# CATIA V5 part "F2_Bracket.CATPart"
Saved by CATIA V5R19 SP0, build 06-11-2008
Part number: F2
Revision: ANY
Definition: UNKNOWN
Nomenclature: F2
Source: Unknown
Bounding box of the stored display mesh (mm): x -12.5 to 12.501, y -26.5 to 11, z -24.25 to 24.25
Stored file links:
  C:\Users\Rémi\Documents\BTS CPI\Projet 04- Guitar Elec\Maquette\F2_Bracket.CATPart
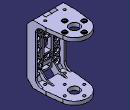
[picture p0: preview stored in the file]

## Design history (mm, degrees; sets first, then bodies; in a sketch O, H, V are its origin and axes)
Set1 "FaceKO#NONE#3497"
  DatumSurface1 "Sur3497_1"
  Line1 "Crv3497_1": stored without definition
Set2 "FaceKO#NONE#11526"
  DatumSurface2 "Sur11526_1"
  Line2 "Crv11526_1": stored without definition
Body1 "Mirror6" (main body)
  Solid1: solid without history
